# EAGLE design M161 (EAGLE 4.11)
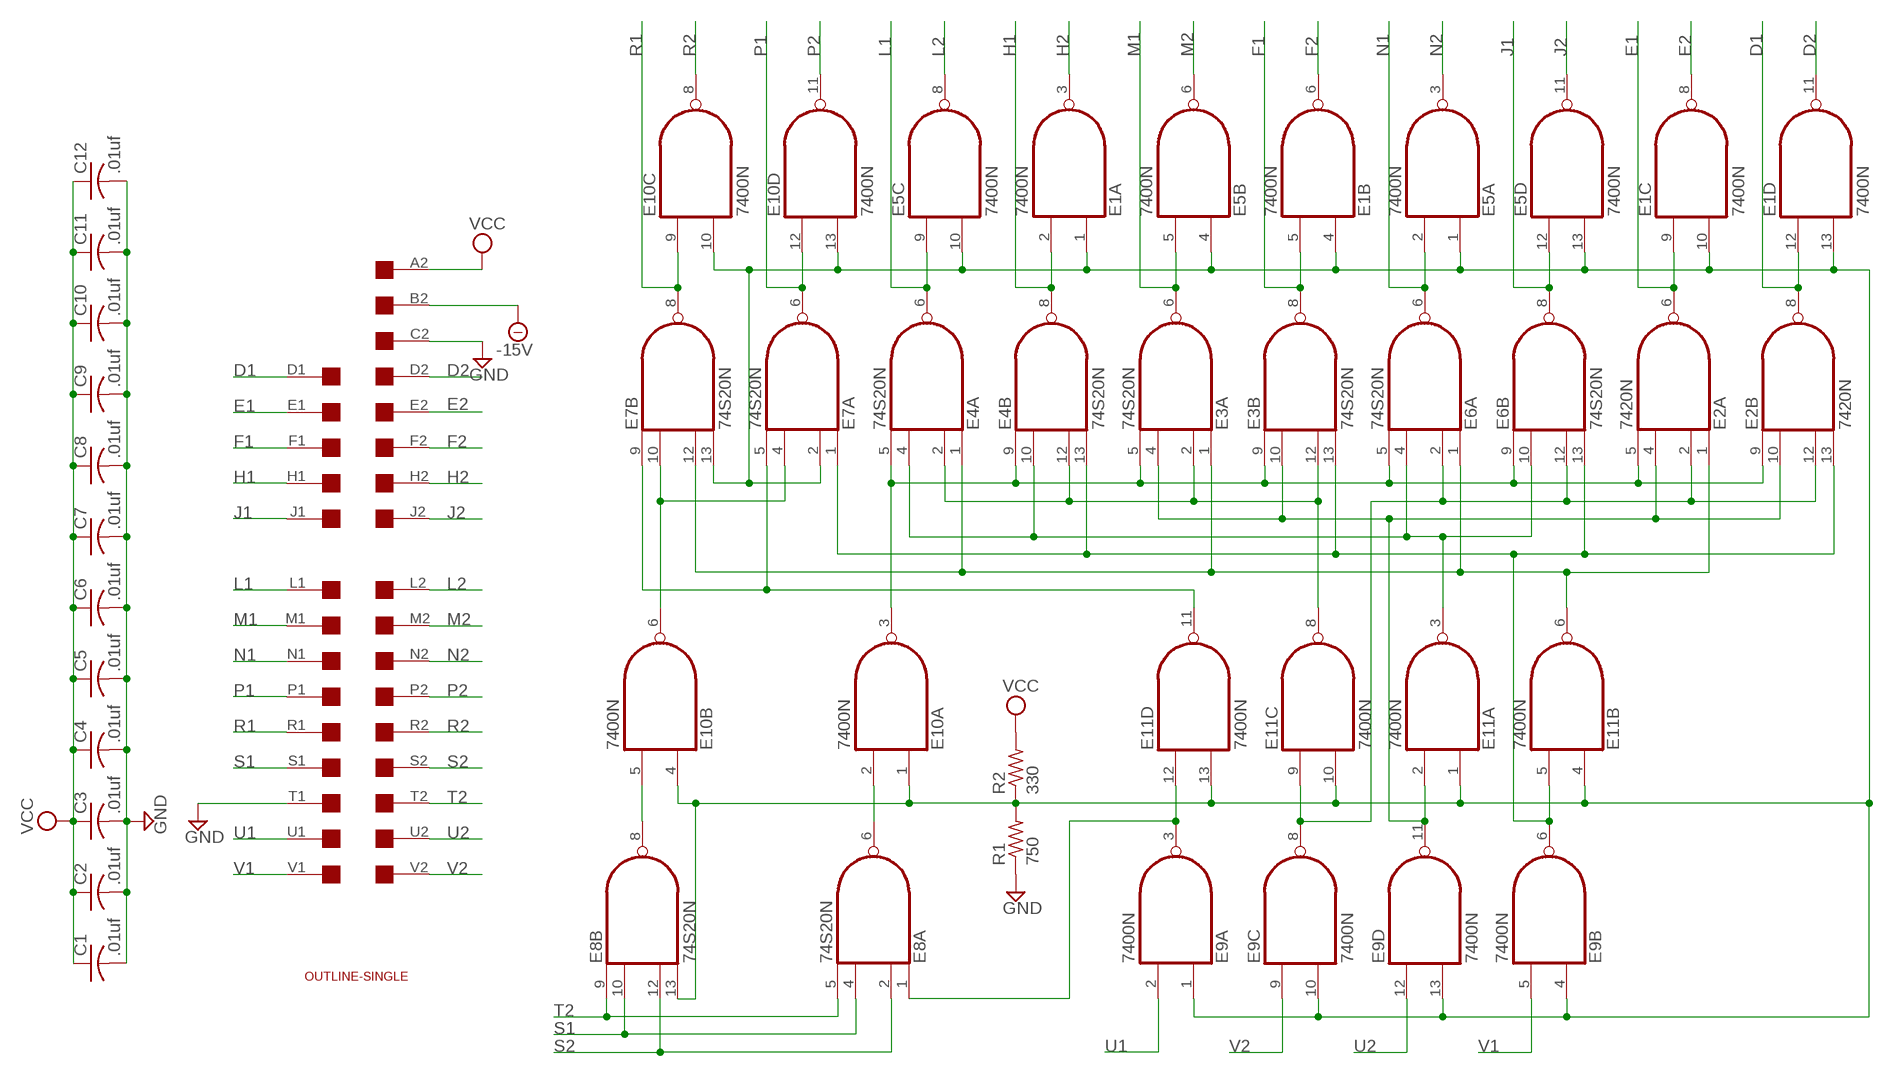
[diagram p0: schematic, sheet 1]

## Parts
C1  .01uf  C-US050-025X075  [C050-025X075]
C2  .01uf  C-US050-025X075  [C050-025X075]
C3  .01uf  C-US050-025X075  [C050-025X075]
C4  .01uf  C-US050-025X075  [C050-025X075]
C5  .01uf  C-US050-025X075  [C050-025X075]
C6  .01uf  C-US050-025X075  [C050-025X075]
C7  .01uf  C-US050-025X075  [C050-025X075]
C8  .01uf  C-US050-025X075  [C050-025X075]
C9  .01uf  C-US050-025X075  [C050-025X075]
C10  .01uf  C-US050-025X075  [C050-025X075]
C11  .01uf  C-US050-025X075  [C050-025X075]
C12  .01uf  C-US050-025X075  [C050-025X075]
E1  7400N  [DIL14]
E2  7420N  74S20N  [DIL14]
E3  74S20N  [DIL14]
E4  74S20N  [DIL14]
E5  7400N  [DIL14]
E6  74S20N  [DIL14]
E7  74S20N  [DIL14]
E8  74S20N  [DIL14]
E9  7400N  [DIL14]
E10  7400N  [DIL14]
E11  7400N  [DIL14]
R1  750  R-US_0207/10  [0207/10]
R2  330  R-US_0207/10  [0207/10]
U$1  OUTLINE-SINGLE  [SINGLE]
U$4  SINGLE  [EDGE-CON2]

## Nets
-15V: U$4.B2
D1: E1.12(D:I0) E2.8(B:O) U$4.D1
D2: E1.11(D:O) U$4.D2
E1: E1.9(C:I0) E2.6(A:O) U$4.E1
E2: E1.8(C:O) U$4.E2
F1: E1.5(B:I1) E3.8(B:O) U$4.F1
F2: E1.6(B:O) U$4.F2
GND: C1.2 C2.2 C3.2 C4.2 C5.2 C6.2 C7.2 C8.2 C9.2 C10.2 C11.2 C12.2 R1.1 U$4.C2 U$4.T1
H1: E1.2(A:I1) E4.8(B:O) U$4.H1
H2: E1.3(A:O) U$4.H2
J1: E5.12(D:I0) E6.8(B:O) U$4.J1
J2: E5.11(D:O) U$4.J2
L1: E4.6(A:O) E5.9(C:I0) U$4.L1
L2: E5.8(C:O) U$4.L2
M1: E3.6(A:O) E5.5(B:I1) U$4.M1
M2: E5.6(B:O) U$4.M2
N1: E5.2(A:I1) E6.6(A:O) U$4.N1
N2: E5.3(A:O) U$4.N2
N$1: E1.1(A:I0) E1.4(B:I0) E1.10(C:I1) E1.13(D:I1) E5.1(A:I0) E5.4(B:I0) E5.10(C:I1) E5.13(D:I1) E7.2(A:I1) E7.13(B:I3) E8.13(B:I3) E9.1(A:I0) E9.4(B:I0) E9.10(C:I1) E9.13(D:I1) E10.1(A:I0) E10.4(B:I0) E10.10(C:I1) E10.13(D:I1) E11.1(A:I0) E11.4(B:I0) E11.10(C:I1) E11.13(D:I1) R1.2 R2.1
N$2: E8.8(B:O) E10.5(B:I1)
N$4: E7.4(A:I2) E7.10(B:I1) E10.6(B:O)
N$5: E2.5(A:I3) E2.9(B:I0) E3.5(A:I3) E3.9(B:I0) E4.5(A:I3) E4.9(B:I0) E6.5(A:I3) E6.9(B:I0) E10.3(A:O)
N$6: E8.6(A:O) E10.2(A:I1)
N$7: E8.1(A:I0) E9.3(A:O) E11.12(D:I0)
N$8: E2.2(A:I1) E2.12(B:I2) E6.2(A:I1) E6.12(B:I2) E9.8(C:O) E11.9(C:I0)
N$9: E2.4(A:I2) E2.10(B:I1) E3.4(A:I2) E3.10(B:I1) E9.11(D:O) E11.2(A:I1)
N$10: E2.13(B:I3) E3.13(B:I3) E4.13(B:I3) E6.13(B:I3) E7.1(A:I0) E9.6(B:O) E11.5(B:I1)
N$11: E3.2(A:I1) E3.12(B:I2) E4.2(A:I1) E4.12(B:I2) E11.8(C:O)
N$12: E7.5(A:I3) E7.9(B:I0) E11.11(D:O)
N$24: E4.4(A:I2) E4.10(B:I1) E6.4(A:I2) E6.10(B:I1) E11.3(A:O)
N$25: E2.1(A:I0) E3.1(A:I0) E4.1(A:I0) E6.1(A:I0) E7.12(B:I2) E11.6(B:O)
P1: E7.6(A:O) E10.12(D:I0) U$4.P1
P2: E10.11(D:O) U$4.P2
R1: E7.8(B:O) E10.9(C:I0) U$4.R1
R2: E10.8(C:O) U$4.R2
S1: E8.4(A:I2) E8.10(B:I1) U$4.S1
S2: E8.2(A:I1) E8.12(B:I2) U$4.S2
T2: E8.5(A:I3) E8.9(B:I0) U$4.T2
U1: E9.2(A:I1) U$4.U1
U2: E9.12(D:I0) U$4.U2
V1: E9.5(B:I1) U$4.V1
V2: E9.9(C:I0) U$4.V2
VCC: C1.1 C2.1 C3.1 C4.1 C5.1 C6.1 C7.1 C8.1 C9.1 C10.1 C11.1 C12.1 R2.2 U$4.A2
Unconnected: U$4.A1 U$4.B1 U$4.C1 U$4.K1 U$4.K2

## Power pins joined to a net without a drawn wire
GND: E1.7(P:GND) E2.7(P:GND) E3.7(P:GND) E4.7(P:GND) E5.7(P:GND) E6.7(P:GND) E7.7(P:GND) E8.7(P:GND) E9.7(P:GND) E10.7(P:GND) E11.7(P:GND)
VCC: E1.14(P:VCC) E2.14(P:VCC) E3.14(P:VCC) E4.14(P:VCC) E5.14(P:VCC) E6.14(P:VCC) E7.14(P:VCC) E8.14(P:VCC) E9.14(P:VCC) E10.14(P:VCC) E11.14(P:VCC)

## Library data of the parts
C1-C12 = rcl:C-US: CAPACITOR, American symbol
E1 E5 E9-E11 = 74xx-us:74*00: Quad 2-input NAND gate
E2-E4 E6-E8 = 74xx-us:74*20: Dual 4-input NAND gate
R1 R2 = rcl:R-US_: RESISTOR, American symbol
U$1 = dec-con:OUTLINE-*: Board outlines for DEC boards.
U$4 = dec-con:SINGLE: Single-Height DEC board

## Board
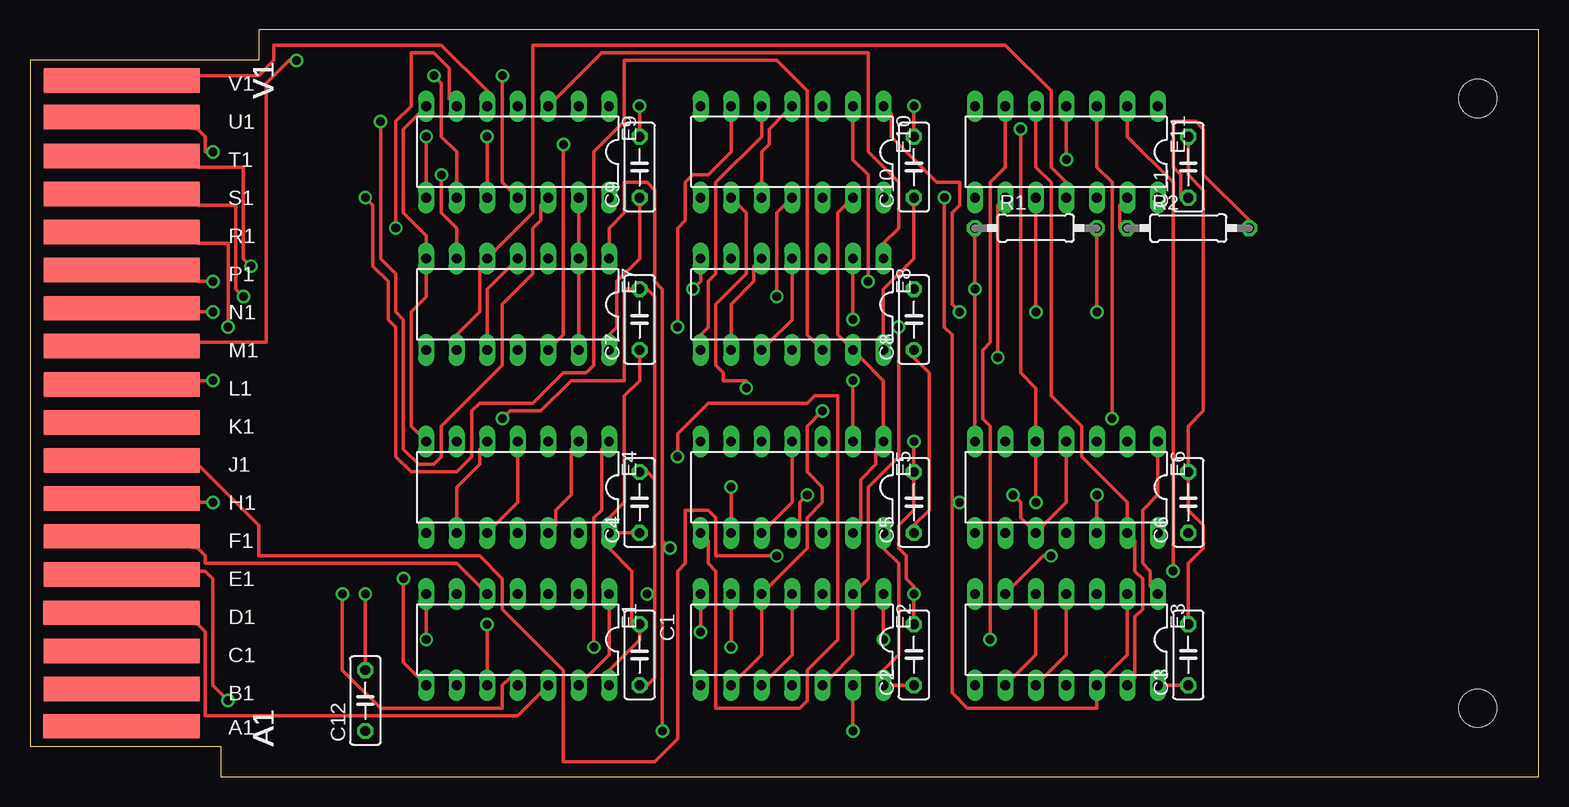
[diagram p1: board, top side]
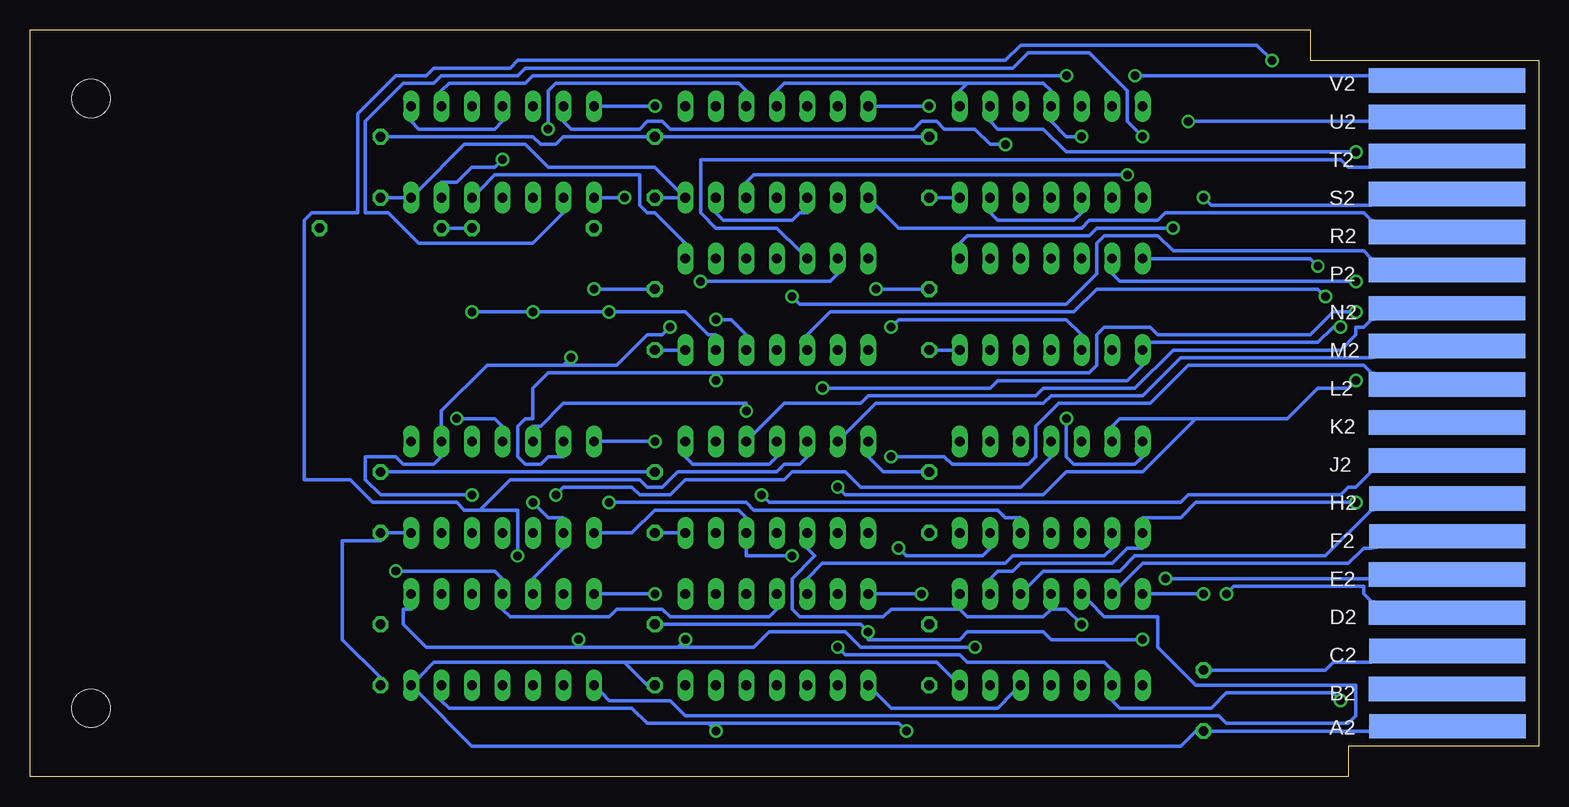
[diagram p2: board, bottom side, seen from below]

Size 125.73 x 62.23 mm. Coordinates in mm from the lower left corner, seen from the top.
Copper layers (1*16): Top 0.035mm / dielectric 1.5mm / Bottom 0.035mm
Design rules "10mils": minimum track width 12mil, minimum drill 28mil, track to track 10mil, track to pad 10mil, pad to pad 10mil, via to via 10mil, smd to smd 10mil, copper to edge 25mil, drill to drill 10mil, minimum pad ring 10mil, minimum via ring 8mil, stop-mask expansion 0mil, vias tented up to drill 0mil, thermal gap 10mil

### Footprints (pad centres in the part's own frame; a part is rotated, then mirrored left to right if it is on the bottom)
C050-025X075 = drill 0.813 octagon: 1 -2.54,0; 2 2.54,0
DIL14 = drill 0.813 long: 1 -7.62,-3.81; 2 -5.08,-3.81; 3 -2.54,-3.81; 4 0,-3.81; 5 2.54,-3.81; 6 5.08,-3.81; 7 7.62,-3.81; 8 7.62,3.81; 9 5.08,3.81; 10 2.54,3.81; 11 0,3.81; 12 -2.54,3.81; 13 -5.08,3.81; 14 -7.62,3.81
0207/10 = drill 0.813 octagon: 1 -5.08,0; 2 5.08,0
SINGLE = hole 3.175: 120.65,56.515; 120.65,5.715
EDGE-CON2 = smd 13.017 x 2.032: A1 7.633,4.207; B1 7.639,7.327; C1 7.636,10.489; D1 7.633,13.665; E1 7.642,16.84; F1 7.642,20.041; H1 7.642,23.19; J1 7.642,26.34; K1 7.642,29.515; L1 7.642,32.69; M1 7.642,35.89; N1 7.642,39.04; P1 7.642,42.24; R1 7.642,45.39; S1 7.642,48.565; T1 7.642,51.74; U1 7.642,54.966; V1 7.642,58.026 | smd 13.017 x 2.032 bottom: A2 7.614,4.207; B2 7.642,7.328; C2 7.617,10.49; D2 7.642,13.665; E2 7.642,16.84; F2 7.617,20.041; H2 7.617,23.19; J2 7.642,26.34; K2 7.642,29.515; L2 7.642,32.69; M2 7.642,35.89; N2 7.642,39.04; P2 7.642,42.24; R2 7.642,45.39; S2 7.642,48.565; T2 7.642,51.74; U2 7.642,54.966; V2 7.642,58.026

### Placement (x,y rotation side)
C1  50.8,10.16 270 top
C2  73.66,10.16 90 top
C3  96.52,10.16 90 top
C4  50.8,22.86 90 top
C5  73.66,22.86 90 top
C6  96.52,22.86 90 top
C7  50.8,38.1 90 top
C8  73.66,38.1 90 top
C9  50.8,50.8 90 top
C10  73.66,50.8 90 top
C11  96.52,50.8 90 top
C12  27.94,6.35 90 top
E1  40.64,11.43 180 top
E2  63.5,11.43 180 top
E3  86.36,11.43 180 top
E4  40.64,24.13 180 top
E5  63.5,24.13 180 top
E6  86.36,24.13 180 top
E7  40.64,39.37 180 top
E8  63.5,39.37 180 top
E9  40.64,52.07 180 top
E10  63.5,52.07 180 top
E11  86.36,52.07 180 top
R1  83.82,45.72 0 top
R2  96.52,45.72 0 top
U$1  0,0 0 top
U$4  0,0 0 top

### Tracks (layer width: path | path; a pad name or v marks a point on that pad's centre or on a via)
D1
  Top 0.305: E1.12 42.55,6.99 40.64,5.08 14.61,5.08 14.61,12.06 13.97,12.7 U$4.D1
  Bottom 0.305: E1.12 43.82,6.99 45.09,5.71 53.98,5.71 55.25,6.99 E2.8
D2  (via drill 0.71)
  Top 0.305: v26.04,15.24 26.04,8.89 29.21,5.71 39.37,5.71 39.37,7.62 40.01,8.26 E1.11
  Bottom 0.305: v26.04,15.24 25.4,15.88 14.61,15.88 14.61,15.24 13.97,14.61 U$4.D2
E1  (via drill 0.71)
  Top 0.305: v58.42,10.79 58.42,13.97 E2.6 | v16.51,6.35 15.24,7.62 15.24,16.51 14.61,17.14 13.97,17.14 U$4.E1
  Bottom 0.305: v58.42,10.79 57.79,10.16 48.26,10.16 47.63,9.53 36.2,9.53 35.56,8.89 E1.9 35.56,6.35 34.93,5.71 27.31,5.71 26.04,6.99 17.15,6.99 v16.51,6.35
E2  (via drill 0.71)
  Top 0.305: v31.12,16.51 31.12,9.53 32.39,8.26 E1.8
  Bottom 0.305: v31.12,16.51 13.97,16.51 U$4.E2
F1
  Top 0.305: E1.5 37.47,15.88 35.56,17.78 14.61,17.78 14.61,18.41 13.97,19.05 U$4.F1
  Bottom 0.305: E3.8 78.11,6.99 77.47,6.35 72.39,6.35 71.12,5.08 26.67,5.08 26.04,4.45 15.88,4.45 15.24,5.08 15.24,7.62 28.58,7.62 31.75,10.79 31.75,13.34 36.2,13.34 37.47,14.61 E1.5
F2
  Bottom 0.305: E1.6 34.93,15.88 33.02,17.78 15.88,17.78 14.61,19.05 13.97,19.05 U$4.F2
GND  (via drill 0.71)
  Top 0.305: v50.8,55.88 50.8,53.98 C9.2 | v73.66,55.88 73.66,53.98 C10.2 | C3.2 96.52,13.34 96.52,17.78 97.79,19.05 97.79,20.95 96.52,22.23 96.52,24.77 C6.2 96.52,26.04 96.52,29.21 97.79,30.48 97.79,48.9 96.52,50.16 96.52,52.7 C11.2 | v73.66,27.94 73.66,26.04 C5.2 73.66,24.77 73.66,22.23 72.39,20.95 72.39,19.05 73.03,18.41 73.03,16.51 73.66,15.88 v73.66,15.24 73.66,13.34 C2.2 | R1.1 78.74,45.09 v78.74,40.64 78.74,29.21 E6.7 | v27.94,15.24 27.94,9.53 C12.2 | E4.7 32.39,28.57 31.75,29.21 31.75,38.73 33.02,40.01 33.02,41.91 E7.7 33.02,44.45 33.02,45.09 31.12,46.99 31.12,53.98 32.39,55.24 E9.7 | v55.25,40.64 55.88,41.27 55.88,41.91 E8.7 | 52.07,15.24 52.07,24.77 | 52.07,15.24 52.07,8.26 51.44,7.62 C1.2 | 52.07,24.77 51.44,25.4 C4.2 | v51.44,15.24 52.07,15.24 | v55.88,12.06 55.88,13.97 E2.7 | 52.07,24.77 52.07,40.01 51.44,40.64 C7.2 50.17,40.64 49.53,40.64 49.53,33.02 45.09,33.02 42.55,30.48 40.01,30.48 v39.37,29.84 | v18.42,42.55 17.78,43.18 17.78,50.8 13.97,50.8 U$4.T1 | v33.02,11.43 33.02,13.97 E1.7
  Bottom 0.305: v50.8,55.88 55.25,55.88 E10.7 | v73.66,55.88 78.11,55.88 E11.7 | C11.2 95.89,53.34 83.82,53.34 83.19,52.7 81.92,52.7 81.28,53.34 74.3,53.34 C10.2 73.03,53.34 51.44,53.34 C9.2 | v73.66,27.94 78.11,27.94 E6.7 | v78.74,40.64 74.3,40.64 C8.2 | C6.2 95.89,25.4 74.3,25.4 C5.2 | U$4.C2 13.97,9.53 17.15,9.53 17.78,8.89 27.31,8.89 C12.2 | v27.94,15.24 32.39,15.24 E1.7 | v55.25,40.64 51.44,40.64 C7.2 | v73.66,15.24 78.11,15.24 E3.7 | v51.44,15.24 55.25,15.24 E2.7 | E5.7 55.88,26.67 54.61,25.4 51.44,25.4 C4.2 | C2.2 73.03,12.7 56.52,12.7 v55.88,12.06 55.88,11.43 48.26,11.43 47.63,12.06 41.28,12.06 40.64,11.43 v33.02,11.43 | v39.37,29.84 39.37,26.67 38.74,26.04 33.66,26.04 33.02,26.67 E4.7 | v18.42,42.55 19.05,43.18 32.39,43.18 E7.7
H1  (via drill 0.71)
  Top 0.305: v15.24,22.86 13.97,22.86 U$4.H1
  Bottom 0.305: v15.24,22.86 28.58,22.86 29.85,21.59 33.02,21.59 E4.8 33.02,19.05 34.29,19.05 35.56,17.78 43.18,17.78 43.82,17.14 45.09,17.14 45.72,16.51 E1.2
H2
  Bottom 0.305: E1.3 42.55,15.88 41.28,17.14 34.93,17.14 33.66,18.41 17.78,18.41 13.97,22.23 U$4.H2
J1  (via drill 0.71)
  Top 0.305: v62.23,18.41 57.15,18.41 57.15,21.59 56.52,22.23 54.61,22.23 54.61,17.78 53.98,17.14 53.98,3.17 52.07,1.27 44.45,1.27 44.45,8.89 39.37,13.97 39.37,16.51 37.47,18.41 19.05,18.41 19.05,20.95 13.97,26.04 U$4.J1
  Bottom 0.305: E6.8 78.11,20.32 75.57,20.32 73.66,22.23 66.68,22.23 66.04,21.59 E5.12 66.04,19.05 66.04,18.41 v62.23,18.41
J2  (via drill 0.71)
  Top 0.305: v64.77,23.5 64.14,22.86 64.14,20.95 E5.11
  Bottom 0.305: v64.77,23.5 64.14,22.86 29.85,22.86 29.21,23.5 16.51,23.5 15.88,24.13 15.24,24.13 13.97,25.4 U$4.J2
L1  (via drill 0.71)
  Top 0.305: v15.24,33.02 13.97,33.02 U$4.L1 | v58.42,24.13 58.42,21.59 E5.9
  Bottom 0.305: v15.24,33.02 15.88,32.38 18.42,32.38 20.96,29.84 28.58,29.84 | 28.58,29.84 34.93,29.84 35.56,29.21 E4.6 | v58.42,24.13 57.79,23.5 41.28,23.5 39.37,25.4 33.02,25.4 28.58,29.84
L2  (via drill 0.71)
  Top 0.305: v53.98,26.67 53.98,28.57 56.52,31.11 64.77,31.11 65.41,31.75 67.31,31.75 67.31,11.43 64.77,8.89 64.77,6.35 64.14,5.71 57.15,5.71 57.15,17.14 56.52,17.78 56.52,19.68 E5.8
  Bottom 0.305: v53.98,26.67 49.53,26.67 48.9,26.04 42.55,26.04 41.91,26.67 41.91,29.21 40.01,31.11 32.39,31.11 29.21,34.29 14.61,34.29 13.97,33.66 U$4.L2
M1  (via drill 0.71)
  Top 0.305: v22.23,59.69 21.59,59.69 19.69,57.78 19.69,36.2 13.97,36.2 U$4.M1 | v85.09,18.41 84.46,18.41 81.92,15.88 E3.6
  Bottom 0.305: v22.23,59.69 23.5,60.96 43.18,60.96 44.45,59.69 85.09,59.69 85.73,59.05 92.08,59.05 92.71,58.42 95.25,58.42 98.43,55.24 98.43,46.99 102.24,46.99 102.87,46.35 102.87,24.77 99.06,24.77 97.16,22.86 90.17,22.86 89.54,22.23 88.27,22.23 | 88.27,22.23 85.73,24.77 74.93,24.77 74.3,24.13 73.03,24.13 71.76,25.4 63.5,25.4 62.87,26.04 61.6,26.04 60.96,26.67 E5.5 | v85.09,18.41 85.09,22.23 88.27,22.23
M2
  Bottom 0.305: E5.6 57.79,28.57 55.25,31.11 41.28,31.11 40.64,31.75 33.02,31.75 29.85,34.92 13.97,34.92 U$4.M2
N1  (via drill 0.71)
  Top 0.305: v15.24,38.73 13.97,38.73 U$4.N1 | v68.58,33.02 68.58,29.21 E5.2
  Bottom 0.305: v15.24,38.73 17.15,38.73 19.05,36.83 31.75,36.83 32.39,37.47 36.2,37.47 36.83,36.83 36.83,34.29 37.47,33.66 68.58,33.66 | 68.58,33.66 82.55,33.66 83.82,32.38 83.82,29.84 84.46,29.84 85.09,29.21 85.09,26.67 84.46,26.04 83.19,26.04 82.55,26.67 81.28,26.67 E6.6 | 68.58,33.66 v68.58,33.02
N2
  Bottom 0.305: E5.3 65.41,28.57 62.87,31.11 56.52,31.11 55.88,31.75 41.91,31.75 41.28,32.38 33.66,32.38 30.48,35.56 16.51,35.56 15.24,36.83 15.24,37.47 14.61,37.47 13.97,38.1 U$4.N2
N$1  (via drill 0.71)
  Top 0.305: E9.13 45.72,46.99 45.72,44.45 E7.2 45.72,41.91 45.72,36.83 E7.13 | E10.4 62.87,55.24 61.6,53.98 61.6,52.7 60.96,52.07 60.96,49.53 E10.10 | v38.1,53.34 38.1,49.53 E9.10 | v38.1,12.7 38.1,8.89 E1.10 | E1.13 46.36,8.26 48.26,10.16 48.26,13.97 E1.1 | E5.10 61.6,20.95 63.5,22.86 63.5,26.67 E5.4 | E11.13 90.81,47.62 90.81,45.72 R2.1 | E5.13 69.22,20.95 69.22,24.77 70.49,26.04 70.49,27.3 E5.1 71.12,29.21 71.12,33.02 69.22,34.92 E8.13 67.95,36.2 67.31,36.83 67.31,46.99 67.95,47.62 E10.13 | v83.82,38.73 83.82,46.99 E11.10 | v77.47,38.73 76.84,39.37 76.84,46.99 77.47,47.62 77.47,49.53 75.57,49.53 71.76,53.34 71.76,55.24 E10.1 | v88.9,38.73 88.9,45.09 R1.2 | v86.36,51.44 86.36,54.61 E11.4
  Bottom 0.305: E9.10 38.1,46.99 38.74,46.35 45.09,46.35 45.72,46.99 E9.13 | 47.63,57.78 41.28,57.78 40.64,57.15 E9.4 40.64,54.61 39.37,53.34 v38.1,53.34 | 47.63,57.78 48.26,57.15 E9.1 | E10.10 60.96,46.99 61.6,46.99 62.23,46.35 67.95,46.35 68.58,46.99 E10.13 | 47.63,57.78 62.87,57.78 63.5,57.15 E10.4 | v38.1,12.7 39.37,13.97 40.64,13.97 | 40.64,13.97 E1.4 40.64,13.97 | 40.64,13.97 41.28,13.34 47.63,13.34 48.26,13.97 | 48.26,13.97 E1.1 48.26,13.97 | E11.4 86.36,54.61 87,53.98 93.35,53.98 93.98,54.61 E11.1 | R1.2 89.54,45.72 90.81,45.72 R2.1 | E8.13 68.58,36.83 69.22,36.83 71.12,38.73 v77.47,38.73 v83.82,38.73 v88.9,38.73 | v86.36,51.44 87,50.8 88.9,50.8 90.17,49.53 91.44,49.53 E11.13 | E5.4 63.5,26.67 64.14,26.04 70.49,26.04 71.12,26.67 E5.1 | 48.26,13.97 53.98,13.97 54.61,13.34 61.6,13.34 62.23,13.97 62.23,16.51 60.33,18.41 60.96,19.05 E5.10
N$2
  Top 0.305: E8.8 55.88,36.83 56.52,37.47 56.52,41.27 57.15,41.91 57.15,49.53 60.96,53.34 60.96,54.61 E10.5
N$4  (via drill 0.71)
  Top 0.305: E7.4 40.01,42.55 38.1,40.64 38.1,36.83 E7.10 | v53.98,37.47 53.98,45.72 54.61,46.35 54.61,49.53 55.25,50.16 56.52,50.16 58.42,52.07 58.42,54.61 E10.6
  Bottom 0.305: v53.98,37.47 53.34,38.1 39.37,38.1 38.1,36.83 E7.10
N$5  (via drill 0.71)
  Top 0.305: E2.9 59.06,8.26 60.96,10.16 60.96,13.97 E2.5 61.6,15.88 64.77,19.05 64.77,21.59 66.04,22.86 66.04,24.13 64.77,25.4 64.77,29.21 v66.04,30.48 | E4.9 35.56,21.59 35.56,24.13 37.47,26.04 37.47,27.3 E4.5 | E3.9 81.92,8.26 83.82,10.16 83.82,13.97 E3.5 | v83.82,22.86 83.82,26.67 E6.5 83.82,29.21 83.82,32.38 82.55,33.66 v82.55,53.98
  Bottom 0.305: E2.5 60.96,16.51 59.69,17.78 44.45,17.78 43.82,18.41 36.2,18.41 35.56,19.05 E4.9 | v83.82,22.86 82.55,21.59 81.28,21.59 E6.9 81.28,19.05 83.82,16.51 E3.5 | v82.55,53.98 82.55,57.15 81.92,57.78 66.68,57.78 66.04,57.15 E10.3 | v66.04,30.48 66.04,31.11 81.28,31.11 83.19,29.21 83.82,29.21 E6.5
N$6  (via drill 0.71)
  Top 0.305: v69.85,41.27 69.85,50.16 68.58,51.44 68.58,54.61 E10.2
  Bottom 0.305: v69.85,41.27 59.06,41.27 58.42,41.91 E8.6
N$7
  Top 0.305: E9.3 43.82,56.52 47.63,60.33 69.85,60.33 69.85,52.07 72.39,49.53 72.39,45.72 71.12,44.45 E8.1
  Bottom 0.305: E8.1 71.12,44.45 73.66,46.99 74.3,46.99 74.93,47.62 74.93,50.16 87,50.16 88.27,48.9 E11.12
N$8  (via drill 0.71)
  Top 0.305: E2.12 66.68,8.26 68.58,10.16 68.58,13.97 E2.2 69.22,15.88 69.85,16.51 69.85,24.13 72.39,26.67 v72.39,37.47 | v80.65,34.92 80.65,47.62 E11.9 | v33.02,53.34 33.02,49.53 E9.8 | v88.9,23.5 88.9,21.59 E6.12
  Bottom 0.305: 81.28,34.29 v80.65,34.92 | 81.28,34.29 87.63,34.29 91.44,30.48 91.44,29.21 E6.2 91.44,26.67 92.08,26.04 94.62,26.04 95.25,26.67 97.79,26.67 97.79,24.77 96.52,23.5 v88.9,23.5 | v33.02,53.34 34.29,54.61 34.29,57.15 37.47,60.33 42.55,60.33 43.82,59.05 84.46,59.05 85.09,58.42 91.44,58.42 92.08,57.78 94.62,57.78 97.79,54.61 97.79,46.99 95.89,46.99 93.35,44.45 83.82,44.45 81.28,46.99 E11.9 | v72.39,37.47 73.03,36.83 74.3,36.83 76.84,34.29 81.28,34.29
N$9  (via drill 0.71)
  Top 0.305: E2.10 61.6,8.26 63.5,10.16 63.5,13.97 E2.4 | E3.10 84.46,8.26 86.36,10.16 86.36,13.97 E3.4 | v39.37,58.42 39.37,49.53 40.01,48.9 E9.11 | v95.25,17.14 95.25,49.53 91.44,53.34 91.44,54.61 E11.2
  Bottom 0.305: E2.4 63.5,13.97 64.14,13.34 72.39,13.34 73.03,13.97 76.84,13.97 77.47,13.34 85.73,13.34 86.36,13.97 E3.4 86.36,16.51 87,17.14 v95.25,17.14 | v39.37,58.42 83.82,58.42 84.46,57.78 90.81,57.78 91.44,57.15 E11.2
N$10  (via drill 0.71)
  Top 0.305: 52.71,19.68 v53.34,19.05 | 52.71,19.68 52.71,40.64 52.07,41.27 52.07,48.9 51.44,49.53 49.53,49.53 49.53,46.99 48.26,45.72 48.26,44.45 E7.1 | v30.48,45.72 30.48,54.61 31.75,55.88 31.75,60.33 33.66,60.33 34.93,59.05 34.93,56.52 E9.6 | E3.13 92.08,8.26 92.08,13.34 92.71,13.97 92.71,16.51 92.08,17.14 92.08,19.68 E6.13 91.44,21.59 91.44,22.86 87.63,26.67 87.63,29.21 85.09,31.75 85.09,49.53 83.82,50.8 83.82,54.61 E11.5 | v68.58,3.81 68.58,6.35 E2.13 | v52.71,3.81 52.71,19.68
  Bottom 0.305: v53.34,19.05 52.71,18.41 46.36,18.41 45.72,19.05 E4.13 | v30.48,45.72 36.83,45.72 37.47,45.09 47.63,45.09 48.26,44.45 E7.1 | 69.22,4.45 v68.58,3.81 | 69.22,4.45 74.3,4.45 75.57,5.71 90.81,5.71 91.44,6.35 E3.13 | v52.71,3.81 53.34,4.45 69.22,4.45
N$11  (via drill 0.71)
  Top 0.305: E4.12 43.82,20.95 43.82,22.23 45.09,23.5 45.09,27.3 E4.2 | E3.2 91.44,13.97 91.44,10.16 89.54,8.26 E3.12 88.9,6.35 88.9,5.71 78.11,5.71 76.84,6.99 76.84,22.86 | v76.2,48.26 76.2,37.47 76.84,36.83 76.84,22.86 | v77.47,22.86 76.84,22.86
  Bottom 0.305: v76.2,48.26 78.11,48.26 E11.8 | v77.47,22.86 66.04,22.86 65.41,22.23 45.09,22.23 44.45,21.59 43.18,21.59 E4.12
N$12
  Top 0.305: E7.9 35.56,36.83 37.47,38.73 37.47,42.55 E7.5 38.74,43.81 41.91,46.99 41.91,60.96 81.28,60.96 85.09,57.15 85.09,50.8 86.36,49.53 E11.11
N$24  (via drill 0.71)
  Top 0.305: E4.10 38.74,20.95 40.64,22.86 40.64,26.67 E4.4 | E6.4 86.36,26.67 86.36,22.86 84.46,20.95 E6.10 83.19,20.95 82.55,21.59 82.55,22.86 v81.92,23.5 | v90.17,29.84 90.17,49.53 88.9,50.8 88.9,54.61 E11.3
  Bottom 0.305: v90.17,29.84 87,29.84 86.36,29.21 E6.4 | v81.92,23.5 81.28,24.13 75.57,24.13 74.93,23.5 72.39,23.5 71.12,24.77 62.87,24.77 62.23,25.4 57.79,25.4 56.52,24.13 43.18,24.13 40.64,26.67 E4.4
N$25  (via drill 0.71)
  Top 0.305: v44.45,52.7 44.45,36.83 43.82,36.2 E7.12 | E3.1 93.35,15.88 93.35,17.14 92.71,17.78 92.71,22.23 93.98,23.5 93.98,26.67 E6.1 | v71.12,11.43 71.12,13.97 E2.1 | v46.99,10.79 46.99,21.59 47.63,22.23 47.63,27.3 E4.1 | v80.01,11.43 80.01,29.21 79.38,29.84 79.38,35.56 80.01,36.2 80.01,49.53 81.28,50.8 81.28,54.61 E11.6
  Bottom 0.305: v44.45,52.7 45.72,52.7 46.99,53.98 49.53,53.98 50.17,54.61 51.44,54.61 52.07,53.98 72.39,53.98 73.03,54.61 74.3,54.61 74.93,53.98 80.65,53.98 81.28,54.61 E11.6 | 71.76,10.79 v71.12,11.43 | 80.01,10.79 92.71,10.79 94.62,12.7 94.62,13.97 93.98,13.97 E3.1 | 71.76,10.79 80.01,10.79 | v46.99,10.79 56.52,10.79 57.79,12.06 64.14,12.06 65.41,10.79 71.76,10.79 | 80.01,10.79 v80.01,11.43
P1  (via drill 0.71)
  Top 0.305: v15.24,41.27 13.97,41.27 U$4.P1 | v34.29,50.16 34.29,46.99 35.56,45.72 35.56,44.45 E7.6
  Bottom 0.305: v15.24,41.27 34.93,41.27 35.56,41.91 E7.6 | v34.29,50.16 65.41,50.16 66.04,49.53 E10.12
P2  (via drill 0.71)
  Top 0.305: v62.23,40.01 62.23,46.99 62.87,47.62 E10.11
  Bottom 0.305: v62.23,40.01 61.6,39.37 39.37,39.37 36.83,41.91 36.83,44.45 36.2,45.09 31.75,45.09 30.48,43.81 14.61,43.81 13.97,43.18 U$4.P2
R1  (via drill 0.71)
  Top 0.305: v16.51,37.47 16.51,44.45 13.97,44.45 U$4.R1 | v59.69,32.38 59.69,33.02 57.79,33.02 57.79,33.66 57.15,34.29 57.15,39.37 59.69,41.91 59.69,46.99 59.06,47.62 E10.9
  Bottom 0.305: v16.51,37.47 17.15,37.47 18.42,36.2 32.39,36.2 E7.8 33.02,34.29 34.29,33.02 45.09,33.02 45.72,32.38 v59.69,32.38
R2
  Bottom 0.305: E10.8 55.25,47.62 53.34,45.72 38.1,45.72 37.47,46.35 31.75,46.35 31.12,46.99 14.61,46.99 13.97,46.35 U$4.R2
S1  (via drill 0.71)
  Top 0.305: v17.78,40.01 17.15,40.64 17.15,47.62 13.97,47.62 U$4.S1 | E8.4 63.5,41.91 63.5,38.1 61.6,36.2 E8.10
  Bottom 0.305: v17.78,40.01 18.42,40.64 36.83,40.64 38.74,38.73 59.06,38.73 60.96,36.83 E8.10
S2  (via drill 0.71)
  Top 0.305: v68.58,38.1 68.58,41.91 E8.2 | v27.94,48.26 28.58,47.62 28.58,42.55 29.85,41.27 29.85,38.1 30.48,37.47 30.48,26.67 31.75,25.4 35.56,25.4 36.83,26.67 36.83,30.48 37.47,31.11 41.91,31.11 44.45,33.66 46.36,33.66 46.99,34.29 46.99,52.07 49.53,54.61 49.53,59.69 62.23,59.69 64.77,57.15 64.77,36.83 65.41,36.2 E8.12
  Bottom 0.305: v68.58,38.1 67.31,38.1 66.04,36.83 E8.12 | v27.94,48.26 27.31,47.62 13.97,47.62 U$4.S2
T2
  Top 0.305: E8.5 60.33,42.55 60.33,41.27 58.42,39.37 58.42,36.83 E8.9
  Bottom 0.305: E8.5 61.6,43.81 63.5,45.72 68.58,45.72 69.85,46.99 69.85,51.44 16.51,51.44 15.88,50.8 13.97,50.8 U$4.T2
U1  (via drill 0.71)
  Top 0.305: v15.24,52.07 14.61,52.07 14.61,53.34 13.97,53.98 U$4.U1
  Bottom 0.305: v15.24,52.07 39.37,52.07 41.28,53.98 45.09,53.98 45.72,54.61 E9.2
U2  (via drill 0.71)
  Top 0.305: v29.21,54.61 29.21,43.18 30.48,41.91 30.48,38.73 31.12,38.1 31.12,27.3 32.39,26.04 33.66,26.04 34.29,26.67 34.29,29.21 39.37,34.29 39.37,39.37 41.91,41.91 41.91,45.72 42.55,46.35 42.55,47.62 E9.12
  Bottom 0.305: v29.21,54.61 13.97,54.61 U$4.U2
V1
  Top 0.305: E9.5 38.1,57.15 34.29,60.96 20.32,60.96 20.32,59.69 19.05,58.42 13.97,58.42 U$4.V1
V2  (via drill 0.71)
  Top 0.305: v33.66,58.42 34.29,57.78 34.29,53.34 35.56,52.07 35.56,49.53 E9.9
  Bottom 0.305: v33.66,58.42 13.97,58.42 U$4.V2
VCC
  Top 0.305: E4.14 48.9,20.32 50.17,20.32 C4.1 | E1.14 48.26,8.89 50.8,11.43 50.8,12.06 C1.1 50.17,12.7 50.17,17.14 48.26,19.05 E4.14 | E7.14 48.26,36.83 48.9,37.47 48.9,41.27 50.8,43.18 50.8,47.62 C9.1 | E4.14 48.26,21.59 49.53,22.86 49.53,31.75 50.8,33.02 50.8,34.92 C7.1 | E3.14 94.62,7.62 95.89,7.62 C3.1 | C2.1 73.03,7.62 71.76,7.62 E2.14 71.12,8.89 72.39,10.16 72.39,17.78 71.12,19.05 E5.14 | R2.2 101.6,46.35 97.79,50.16 97.79,53.98 97.16,54.61 95.25,54.61 95.25,50.8 95.89,50.16 95.89,48.26 C11.1 | E8.14 71.12,36.83 71.12,40.64 73.66,43.18 73.66,47.62 C10.1 | C5.1 73.66,20.95 74.93,22.23 74.93,33.66 73.66,34.92 C8.1
  Bottom 0.305: U$4.A2 13.97,3.81 27.31,3.81 C12.1 28.58,3.81 29.85,2.54 88.9,2.54 93.35,6.99 E3.14 93.35,8.26 92.08,9.53 76.2,9.53 | E7.14 48.9,35.56 50.17,35.56 C7.1 | E9.14 48.9,48.26 50.17,48.26 C9.1 | E6.14 94.62,20.32 95.89,20.32 C6.1 96.52,19.68 99.7,19.68 99.7,11.43 96.52,8.26 C3.1 | E5.14 71.76,20.32 73.03,20.32 C5.1 | C11.1 95.89,48.26 94.62,48.26 E11.14 93.35,48.9 89.54,52.7 84.46,52.7 82.55,50.8 73.66,50.8 71.76,48.9 E10.14 71.76,48.26 73.03,48.26 C10.1 | E8.14 71.76,35.56 73.03,35.56 C8.1 | 76.2,9.53 74.3,7.62 C2.1 | 76.2,9.53 50.17,9.53 48.9,8.26 E1.14

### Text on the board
tNames: V1 | V1 | V1 | V1 | V1 | V1 | V1 | V1 | V1 | V1 | V1 | V1 | V1 | V1 | V1 | V1 | V1 | V1 | V1 | V1 | V1 | V1 | V1 | V1 | V1 | V1 | V1 | V1 | V1 | V1 | V1 | V1 | A1 | A1 | A1 | A1 | A1 | A1 | A1 | A1 | A1 | A1 | A1 | A1 | A1 | A1 | A1 | A1 | A1 | A1 | A1 | A1 | A1 | A1 | A1 | A1 | A1 | A1 | A1 | A1 | A1 | A1 | A1 | A1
